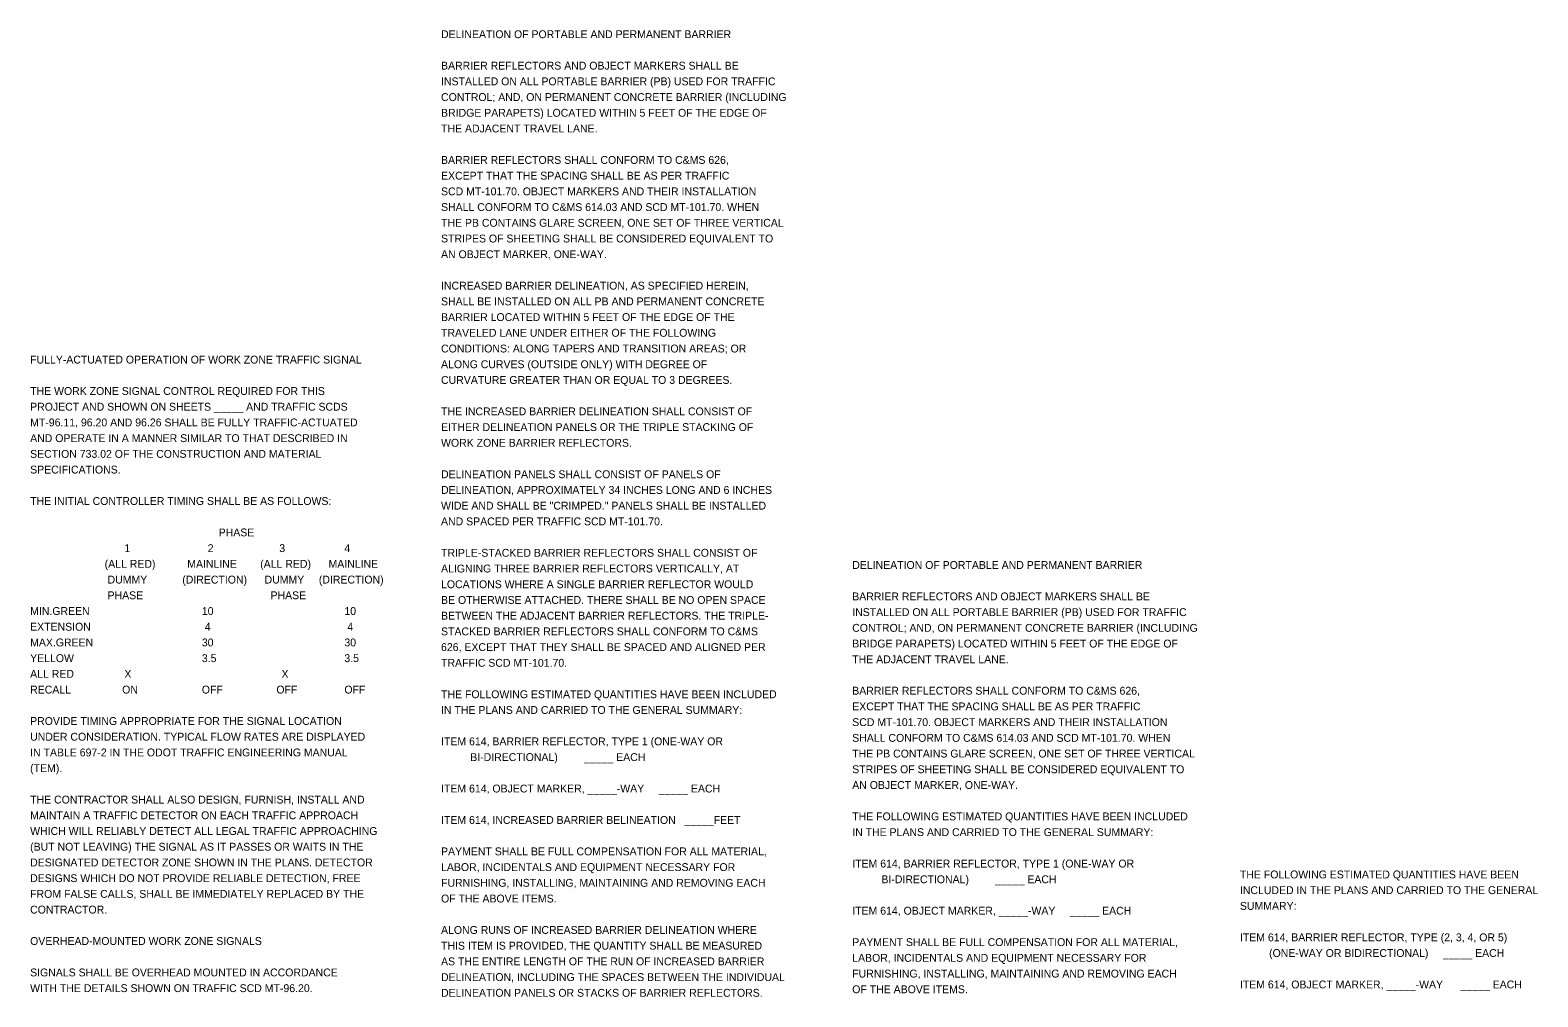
# Model space of a CAD drawing. Extents: x 0 to 63.3, y -2.5 to 22.
# Drawn here: x 36.39 to 63.26, y 0.67 to 17.89 of the extents above; entities that cross this region are included whole.
import ezdxf

# ---------------------------------------------------------------- set-up
doc = ezdxf.new("R2010")
doc.units = 0
doc.layers.add('SH_Text', color=7, linetype='Continuous')

msp = doc.modelspace()

# ---------------------------------------------------------------- texts
at = {"layer": 'SH_Text'}
for s, p in [('DELINEATION OF PORTABLE AND PERMANENT BARRIER', (43.715, 17.748)), ('BARRIER REFLECTORS AND OBJECT MARKERS SHALL BE', (43.715, 17.188)), ('INSTALLED ON ALL PORTABLE BARRIER (PB) USED FOR TRAFFIC', (43.715, 16.908)), ('CONTROL; AND, ON PERMANENT CONCRETE BARRIER (INCLUDING', (43.715, 16.628)), ('BRIDGE PARAPETS) LOCATED WITHIN 5 FEET OF THE EDGE OF', (43.715, 16.348)), ('THE ADJACENT TRAVEL LANE.', (43.715, 16.068)), ('BARRIER REFLECTORS SHALL CONFORM TO C&MS 626,', (43.715, 15.508)), ('EXCEPT THAT THE SPACING SHALL BE AS PER TRAFFIC', (43.715, 15.228)), ('SCD MT-101.70. OBJECT MARKERS AND THEIR INSTALLATION', (43.715, 14.948)), ('SHALL CONFORM TO C&MS 614.03 AND SCD MT-101.70. WHEN', (43.715, 14.668)), ('THE PB CONTAINS GLARE SCREEN, ONE SET OF THREE VERTICAL', (43.715, 14.388)), ('STRIPES OF SHEETING SHALL BE CONSIDERED EQUIVALENT TO', (43.715, 14.108)), ('AN OBJECT MARKER, ONE-WAY.', (43.715, 13.828)), ('INCREASED BARRIER DELINEATION, AS SPECIFIED HEREIN,', (43.715, 13.268)), ('SHALL BE INSTALLED ON ALL PB AND PERMANENT CONCRETE', (43.715, 12.988)), ('BARRIER LOCATED WITHIN 5 FEET OF THE EDGE OF THE', (43.715, 12.708)), ('TRAVELED LANE UNDER EITHER OF THE FOLLOWING', (43.715, 12.428)), ('FULLY-ACTUATED OPERATION OF WORK ZONE TRAFFIC SIGNAL', (36.392, 11.951)), ('CONDITIONS: ALONG TAPERS AND TRANSITION AREAS; OR', (43.715, 12.148)), ('ALONG CURVES (OUTSIDE ONLY) WITH DEGREE OF', (43.715, 11.868)), ('CURVATURE GREATER THAN OR EQUAL TO 3 DEGREES.', (43.715, 11.588)), ('THE WORK ZONE SIGNAL CONTROL REQUIRED FOR THIS', (36.392, 11.391)), ('PROJECT AND SHOWN ON SHEETS _____ AND TRAFFIC SCDS', (36.392, 11.111)), ('THE INCREASED BARRIER DELINEATION SHALL CONSIST OF', (43.715, 11.028)), ('MT-96.11, 96.20 AND 96.26 SHALL BE FULLY TRAFFIC-ACTUATED', (36.392, 10.831)), ('EITHER DELINEATION PANELS OR THE TRIPLE STACKING OF', (43.715, 10.748)), ('AND OPERATE IN A MANNER SIMILAR TO THAT DESCRIBED IN', (36.392, 10.551)), ('WORK ZONE BARRIER REFLECTORS.', (43.715, 10.468)), ('SECTION 733.02 OF THE CONSTRUCTION AND MATERIAL', (36.392, 10.271)), ('SPECIFICATIONS.', (36.392, 9.991)), ('DELINEATION PANELS SHALL CONSIST OF PANELS OF', (43.715, 9.908)), ('DELINEATION, APPROXIMATELY 34 INCHES LONG AND 6 INCHES', (43.715, 9.628)), ('THE INITIAL CONTROLLER TIMING SHALL BE AS FOLLOWS:', (36.392, 9.431)), ('WIDE AND SHALL BE "CRIMPED." PANELS SHALL BE INSTALLED', (43.715, 9.348)), ('AND SPACED PER TRAFFIC SCD MT-101.70.', (43.715, 9.068)), ('PHASE', (39.752, 8.871)), ('1         ', (38.072, 8.591)), ('       2          ', (39.192, 8.591)), ('          3          ', (40.312, 8.591)), ('4', (41.992, 8.591)), ('TRIPLE-STACKED BARRIER REFLECTORS SHALL CONSIST OF', (43.715, 8.508)), ('    (ALL RED)  ', (37.512, 8.311)), ('MAINLINE        (ALL RED)      MAINLINE', (39.192, 8.311)), ('ALIGNING THREE BARRIER REFLECTORS VERTICALLY, AT', (43.715, 8.228)), ('DELINEATION OF PORTABLE AND PERMANENT BARRIER', (51.043, 8.291)), ('     DUMMY            (DIRECTION)      DUMMY     (DIRECTION)', (37.512, 8.031)), ('LOCATIONS WHERE A SINGLE BARRIER REFLECTOR WOULD', (43.715, 7.948)), ('     PHASE                 ', (37.512, 7.751)), ('       PHASE', (40.312, 7.751)), ('BE OTHERWISE ATTACHED. THERE SHALL BE NO OPEN SPACE', (43.715, 7.668)), ('BARRIER REFLECTORS AND OBJECT MARKERS SHALL BE', (51.043, 7.731)), ('MIN.GREEN               ', (36.392, 7.471)), ('     10                    ', (39.192, 7.471)), ('10', (41.992, 7.471)), ('BETWEEN THE ADJACENT BARRIER REFLECTORS. THE TRIPLE-', (43.715, 7.388)), ('INSTALLED ON ALL PORTABLE BARRIER (PB) USED FOR TRAFFIC', (51.043, 7.451)), ('EXTENSION               ', (36.392, 7.191)), ('      4                     ', (39.192, 7.191)), (' 4', (41.992, 7.191)), ('CONTROL; AND, ON PERMANENT CONCRETE BARRIER (INCLUDING', (51.043, 7.171)), ('MAX.GREEN               ', (36.392, 6.911)), ('     30                    ', (39.192, 6.911)), ('30', (41.992, 6.911)), ('STACKED BARRIER REFLECTORS SHALL CONFORM TO C&MS', (43.715, 7.108)), ('BRIDGE PARAPETS) LOCATED WITHIN 5 FEET OF THE EDGE OF', (51.043, 6.891)), ('YELLOW                  ', (36.392, 6.631)), ('     3.5                   ', (39.192, 6.631)), ('3.5', (41.992, 6.631)), ('626, EXCEPT THAT THEY SHALL BE SPACED AND ALIGNED PER', (43.715, 6.828)), ('THE ADJACENT TRAVEL LANE.', (51.043, 6.611)), ('ALL RED      ', (36.392, 6.351)), ('X                     ', (38.072, 6.351)), ('X', (40.872, 6.351)), ('TRAFFIC SCD MT-101.70.', (43.715, 6.548)), ('RECALL       ', (36.392, 6.071)), ('          ON         ', (37.512, 6.071)), ('     OFF        ', (39.192, 6.071)), ('         OFF        ', (40.312, 6.071)), ('OFF', (41.992, 6.071)), ('BARRIER REFLECTORS SHALL CONFORM TO C&MS 626,', (51.043, 6.051)), ('THE FOLLOWING ESTIMATED QUANTITIES HAVE BEEN INCLUDED', (43.715, 5.988)), ('EXCEPT THAT THE SPACING SHALL BE AS PER TRAFFIC', (51.043, 5.771)), ('PROVIDE TIMING APPROPRIATE FOR THE SIGNAL LOCATION', (36.392, 5.511)), ('IN THE PLANS AND CARRIED TO THE GENERAL SUMMARY:', (43.715, 5.708)), ('SCD MT-101.70. OBJECT MARKERS AND THEIR INSTALLATION', (51.043, 5.491)), ('UNDER CONSIDERATION. TYPICAL FLOW RATES ARE DISPLAYED', (36.392, 5.231)), ('ITEM 614, BARRIER REFLECTOR, TYPE 1 (ONE-WAY OR', (43.715, 5.148)), ('SHALL CONFORM TO C&MS 614.03 AND SCD MT-101.70. WHEN', (51.043, 5.211)), ('IN TABLE 697-2 IN THE ODOT TRAFFIC ENGINEERING MANUAL', (36.392, 4.951)), ('          BI-DIRECTIONAL)         _____ EACH', (43.715, 4.868)), ('THE PB CONTAINS GLARE SCREEN, ONE SET OF THREE VERTICAL', (51.043, 4.931)), ('(TEM).', (36.392, 4.671)), ('STRIPES OF SHEETING SHALL BE CONSIDERED EQUIVALENT TO', (51.043, 4.651)), ('ITEM 614, OBJECT MARKER, _____-WAY     _____ EACH', (43.715, 4.308)), ('AN OBJECT MARKER, ONE-WAY.', (51.043, 4.371)), ('THE CONTRACTOR SHALL ALSO DESIGN, FURNISH, INSTALL AND', (36.392, 4.111)), ('MAINTAIN A TRAFFIC DETECTOR ON EACH TRAFFIC APPROACH', (36.392, 3.831)), ('ITEM 614, INCREASED BARRIER BELINEATION   _____FEET', (43.715, 3.748)), ('THE FOLLOWING ESTIMATED QUANTITIES HAVE BEEN INCLUDED', (51.043, 3.811)), ('WHICH WILL RELIABLY DETECT ALL LEGAL TRAFFIC APPROACHING', (36.392, 3.551)), ('IN THE PLANS AND CARRIED TO THE GENERAL SUMMARY:', (51.043, 3.531)), ('(BUT NOT LEAVING) THE SIGNAL AS IT PASSES OR WAITS IN THE', (36.392, 3.271)), ('PAYMENT SHALL BE FULL COMPENSATION FOR ALL MATERIAL,', (43.715, 3.188)), ('DESIGNATED DETECTOR ZONE SHOWN IN THE PLANS. DETECTOR', (36.392, 2.991)), ('LABOR, INCIDENTALS AND EQUIPMENT NECESSARY FOR', (43.715, 2.908)), ('ITEM 614, BARRIER REFLECTOR, TYPE 1 (ONE-WAY OR', (51.043, 2.971)), ('DESIGNS WHICH DO NOT PROVIDE RELIABLE DETECTION, FREE', (36.392, 2.711)), ('FURNISHING, INSTALLING, MAINTAINING AND REMOVING EACH', (43.715, 2.628)), ('          BI-DIRECTIONAL)         _____ EACH', (51.043, 2.691)), ('THE FOLLOWING ESTIMATED QUANTITIES HAVE BEEN', (57.952, 2.777)), ('FROM FALSE CALLS, SHALL BE IMMEDIATELY REPLACED BY THE', (36.392, 2.431)), ('OF THE ABOVE ITEMS.', (43.715, 2.348)), ('INCLUDED IN THE PLANS AND CARRIED TO THE GENERAL', (57.952, 2.497)), ('CONTRACTOR.', (36.392, 2.151)), ('ITEM 614, OBJECT MARKER, _____-WAY     _____ EACH', (51.043, 2.131)), ('SUMMARY:', (57.952, 2.217)), ('ALONG RUNS OF INCREASED BARRIER DELINEATION WHERE', (43.715, 1.788)), ('OVERHEAD-MOUNTED WORK ZONE SIGNALS', (36.392, 1.591)), ('THIS ITEM IS PROVIDED, THE QUANTITY SHALL BE MEASURED', (43.715, 1.508)), ('PAYMENT SHALL BE FULL COMPENSATION FOR ALL MATERIAL,', (51.043, 1.571)), ('ITEM 614, BARRIER REFLECTOR, TYPE (2, 3, 4, OR 5)', (57.952, 1.657)), ('AS THE ENTIRE LENGTH OF THE RUN OF INCREASED BARRIER', (43.715, 1.228)), ('LABOR, INCIDENTALS AND EQUIPMENT NECESSARY FOR', (51.043, 1.291)), ('          (ONE-WAY OR BIDIRECTIONAL)     _____ EACH', (57.952, 1.377)), ('SIGNALS SHALL BE OVERHEAD MOUNTED IN ACCORDANCE', (36.392, 1.031)), ('DELINEATION, INCLUDING THE SPACES BETWEEN THE INDIVIDUAL', (43.715, 0.948)), ('FURNISHING, INSTALLING, MAINTAINING AND REMOVING EACH', (51.043, 1.011)), ('WITH THE DETAILS SHOWN ON TRAFFIC SCD MT-96.20.', (36.392, 0.751)), ('DELINEATION PANELS OR STACKS OF BARRIER REFLECTORS.', (43.715, 0.668)), ('OF THE ABOVE ITEMS.', (51.043, 0.731)), ('ITEM 614, OBJECT MARKER, _____-WAY      _____ EACH', (57.952, 0.817))]:
    msp.add_text(s, height=0.14, dxfattribs=at).set_placement(p)

doc.saveas('drawing.dxf')
